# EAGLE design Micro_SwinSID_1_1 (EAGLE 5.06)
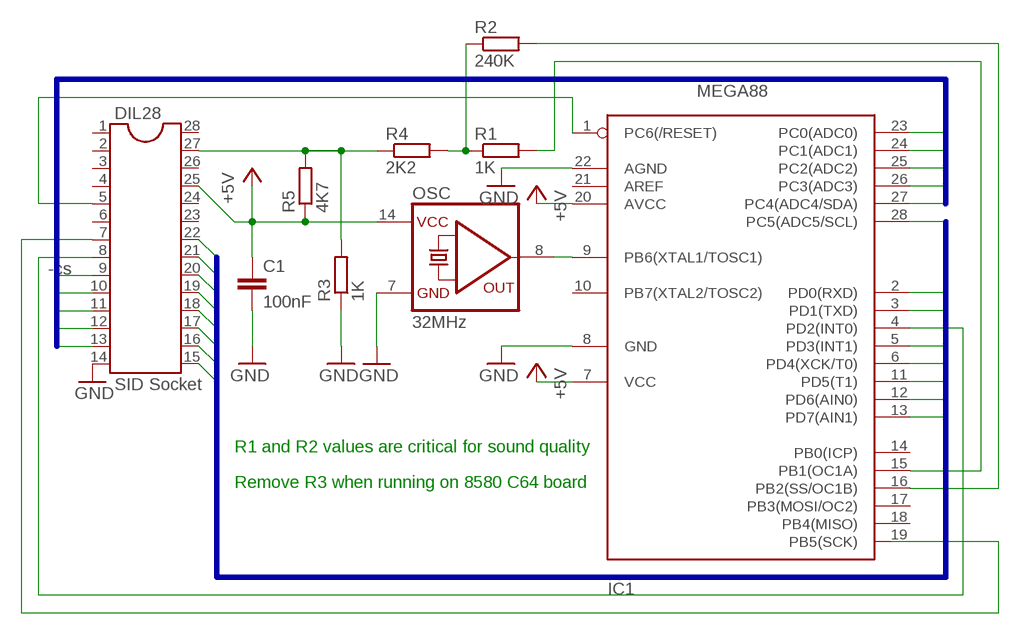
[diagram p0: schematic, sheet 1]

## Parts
C1  100nF  C2.5/2  [C2.5-2]
DIL28  SID Socket  DIL28  [DIL28-6]
IC1  MEGA88  MEGA8-P  [DIL28-3]
OSC  32MHz  QG5860  [DIL14S]
R1  1K  R-EU_0204/7  [0204/7]
R2  240K  R-EU_0204/7  [0204/7]
R3  1K  R-EU_0204/7  [0204/7]
R4  2K2  R-EU_0204/7  [0204/7]
R5  4K7  R-EU_0204/7  [0204/7]

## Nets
+5V: C1.1 DIL28.25 IC1.7(VCC) IC1.20(AVCC) OSC.14(VCC) R5.1
A0: DIL28.9 IC1.23(PC0(ADC0))
A1: DIL28.10 IC1.24(PC1(ADC1))
A2: DIL28.11 IC1.25(PC2(ADC2))
A3: DIL28.12 IC1.26(PC3(ADC3))
A4: DIL28.13 IC1.27(PC4(ADC4/SDA))
D0: DIL28.15 IC1.2(PD0(RXD))
D1: DIL28.16 IC1.3(PD1(TXD))
D2: DIL28.17 IC1.28(PC5(ADC5/SCL))
D3: DIL28.18 IC1.5(PD3(INT1))
D4: DIL28.19 IC1.6(PD4(XCK/T0))
D5: DIL28.20 IC1.11(PD5(T1))
D6: DIL28.21 IC1.12(PD6(AIN0))
D7: DIL28.22 IC1.13(PD7(AIN1))
GND: C1.2 DIL28.14 IC1.8(GND) IC1.22(AGND) OSC.7(GND) R3.1
N$1: IC1.9(PB6(XTAL1/TOSC1)) OSC.8(OUT)
N$2: DIL28.27 R3.2 R4.1 R5.2
N$3: R1.1 R2.1 R4.2
N$4: DIL28.7 IC1.19(PB5(SCK))
N$6: IC1.15(PB1(OC1A)) R1.2
N$7: IC1.16(PB2(SS/OC1B)) R2.2
N$11: DIL28.8 IC1.4(PD2(INT0))
P5: DIL28.5 IC1.1(PC6(/RESET))
Unconnected: DIL28.1 DIL28.2 DIL28.3 DIL28.4 DIL28.6 DIL28.23 DIL28.24 DIL28.26 DIL28.28 IC1.10(PB7(XTAL2/TOSC2)) IC1.14(PB0(ICP)) IC1.17(PB3(MOSI/OC2)) IC1.18(PB4(MISO)) IC1.21(AREF)

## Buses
DATA:D7,D6,D5,D4,D3,D2,D1,D0
ADR:A0,A1,A2,A3,A4

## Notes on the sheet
- -cs
- R1 and R2 values are critical for sound quality
- Remove R3 when running on 8580 C64 board

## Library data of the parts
C1 = capacitor-wima:C: CAPACITOR
DIL28 = ic-package:DIL28: Dual In Line
IC1 = atmel:MEGA8-P: MICROCONTROLLER 8 Kbytes FLASH, 1 kbytes SRAM, 512 bytes EEPROM, USART, 4-channel 10 bit ADC, 2-channel 8 bit ADC Pin compatible with Atmega48, ATMega88, ATMega168 Source: avr.lbr
OSC = crystal:QG5860: CRYSTAL RESONATOR
R1-R5 = rcl:R-EU_: RESISTOR, European symbol

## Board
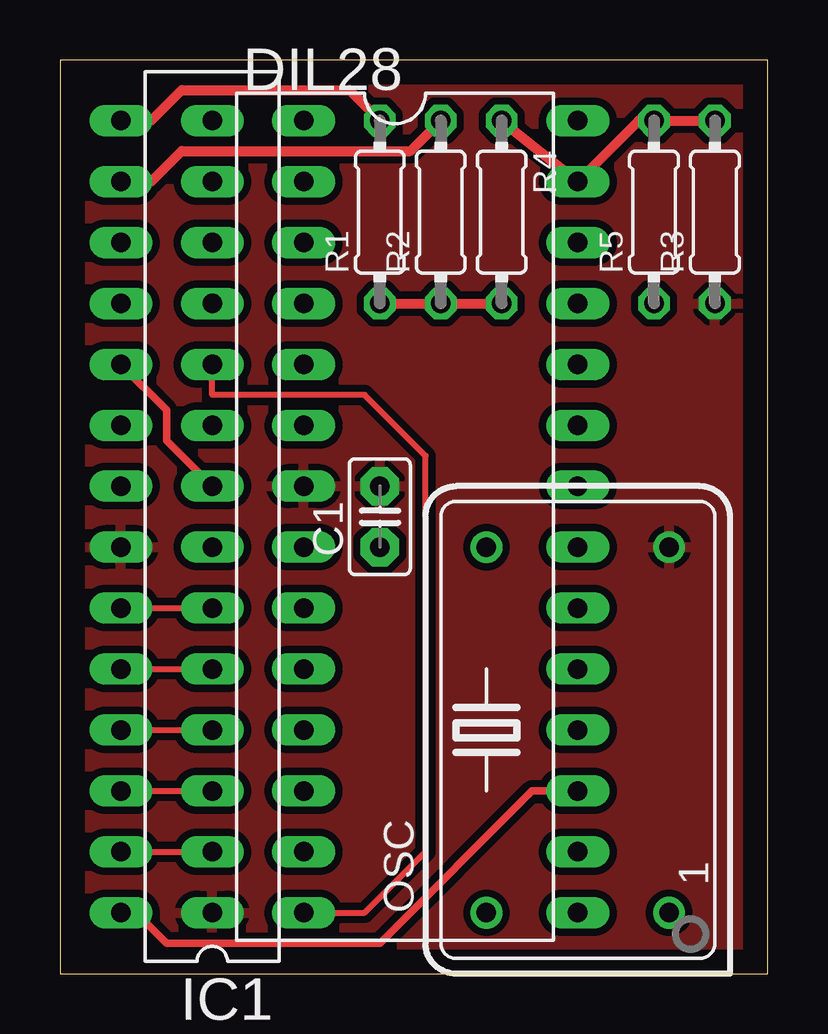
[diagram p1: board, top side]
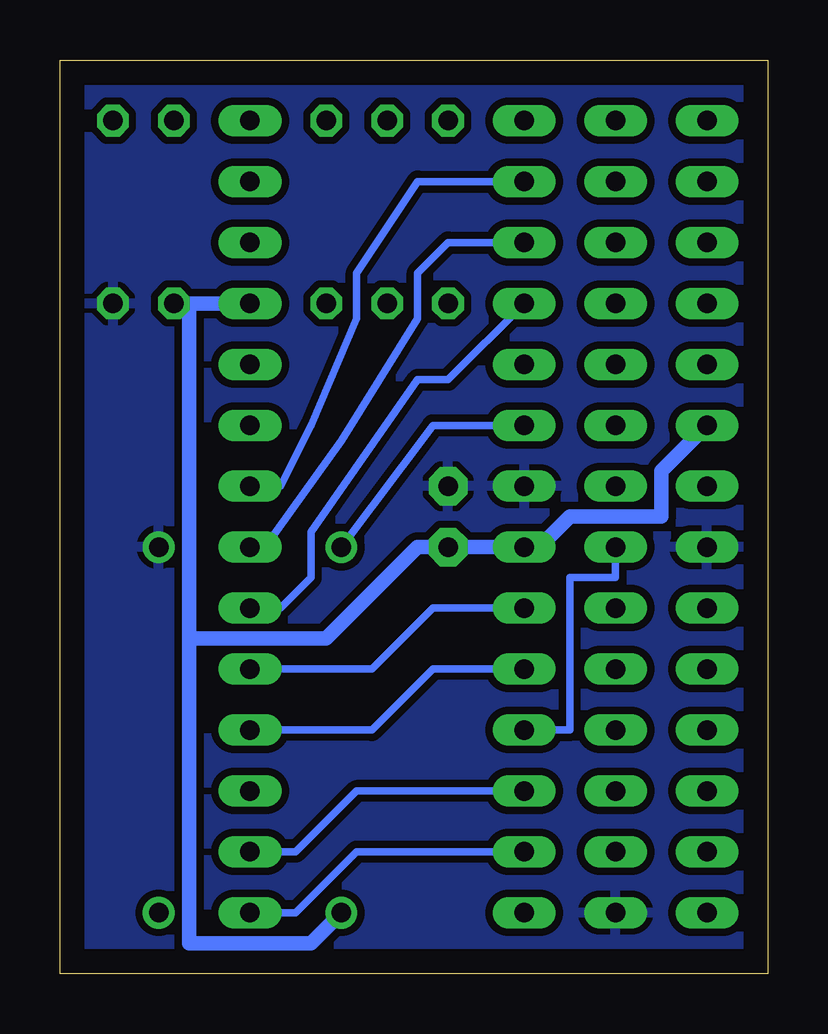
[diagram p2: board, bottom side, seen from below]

Size 29.52 x 38.09 mm. Coordinates in mm from the lower left corner, seen from the top.
Outline: 0,0 29.52,0 29.52,38.09 0,38.09 0,0
Copper layers (1*16): Top 0.035mm / dielectric 1.5mm / Bottom 0.035mm
Design rules "default": minimum track width 10mil, minimum drill 24mil, track to track 8mil, track to pad 8mil, pad to pad 8mil, via to via 8mil, smd to smd 8mil, copper to edge 40mil, drill to drill 8mil, minimum pad ring 10mil, minimum via ring 8mil, stop-mask expansion 4mil, vias tented up to drill 0mil, thermal gap 10mil

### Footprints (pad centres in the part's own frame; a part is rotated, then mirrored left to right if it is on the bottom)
C2.5-2 = drill 0.813 pad 1.6 octagon: 1 -1.27,0; 2 1.27,0
DIL28-6 = drill 0.813 long: 1 -16.51,-7.62; 2 -13.97,-7.62; 3 -11.43,-7.62; 4 -8.89,-7.62; 5 -6.35,-7.62; 6 -3.81,-7.62; 7 -1.27,-7.62; 8 1.27,-7.62; 9 3.81,-7.62; 10 6.35,-7.62; 11 8.89,-7.62; 12 11.43,-7.62; 13 13.97,-7.62; 14 16.51,-7.62; 15 16.51,7.62; 16 13.97,7.62; 17 11.43,7.62; 18 8.89,7.62; 19 6.35,7.62; 20 3.81,7.62; 21 1.27,7.62; 22 -1.27,7.62; 23 -3.81,7.62; 24 -6.35,7.62; 25 -8.89,7.62; 26 -11.43,7.62; 27 -13.97,7.62; 28 -16.51,7.62
DIL28-3 = drill 0.813 long: 1 -16.51,-3.81; 2 -13.97,-3.81; 3 -11.43,-3.81; 4 -8.89,-3.81; 5 -6.35,-3.81; 6 -3.81,-3.81; 7 -1.27,-3.81; 8 1.27,-3.81; 9 3.81,-3.81; 10 6.35,-3.81; 11 8.89,-3.81; 12 11.43,-3.81; 13 13.97,-3.81; 14 16.51,-3.81; 15 16.51,3.81; 16 13.97,3.81; 17 11.43,3.81; 18 8.89,3.81; 19 6.35,3.81; 20 3.81,3.81; 21 1.27,3.81; 22 -1.27,3.81; 23 -3.81,3.81; 24 -6.35,3.81; 25 -8.89,3.81; 26 -11.43,3.81; 27 -13.97,3.81; 28 -16.51,3.81
DIL14S = drill 0.813 round: 1 -7.62,-3.81; 7 7.62,-3.81; 8 7.62,3.81; 14 -7.62,3.81
0204/7 = drill 0.813 octagon: 1 -3.81,0; 2 3.81,0

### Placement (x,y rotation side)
C1  13.34,19.05 90 top
DIL28  13.97,19.05 270 top
IC1  6.35,19.05 90 top
OSC  21.59,10.16 90 top
R1  13.34,31.75 90 top
R2  15.88,31.75 90 top
R3  27.3,31.75 90 top
R4  18.41,31.75 270 top
R5  24.77,31.75 90 top

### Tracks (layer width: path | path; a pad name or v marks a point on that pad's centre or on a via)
+5V
  Bottom 0.406: 24.13,27.94 R5.1
  Bottom 0.61: 24.13,13.97 18.41,13.97 14.61,17.78 C1.1 IC1.7 9.52,17.78 8.25,19.05 4.45,19.05 4.45,20.96 IC1.20 | 24.13,13.97 24.13,27.94 | R5.1 DIL28.25 | OSC.14 19.05,1.27 24.13,1.27 24.13,13.97
A0
  Top 0.254: IC1.23 DIL28.9
A1
  Top 0.254: IC1.24 DIL28.10
A2
  Top 0.254: IC1.25 DIL28.11
A3
  Top 0.254: IC1.26 DIL28.12
A4
  Top 0.254: IC1.27 DIL28.13
D0
  Bottom 0.305: IC1.2 17.14,5.08 19.69,2.54 DIL28.15
D1
  Bottom 0.305: IC1.3 17.14,7.62 19.69,5.08 DIL28.16
D2
  Top 0.305: IC1.28 3.17,2.54 4.45,1.27 13.34,1.27 19.69,7.62 DIL28.17
D3
  Bottom 0.305: IC1.5 13.97,12.7 16.51,10.16 DIL28.18
D4
  Bottom 0.305: IC1.6 13.97,15.24 16.51,12.7 DIL28.19
D5
  Bottom 0.305: IC1.11 13.34,24.77 14.61,24.77 19.05,18.41 19.05,16.51 20.32,15.24 DIL28.20
D6
  Bottom 0.305: IC1.12 13.34,30.48 14.61,29.21 14.61,27.3 17.78,22.23 20.96,17.78 DIL28.21
D7
  Bottom 0.305: IC1.13 14.61,33.02 17.14,29.21 17.14,27.3 19.05,22.86 20.32,20.32 DIL28.22
GND
  pour Bottom (isolate 0.305): 0,38.1 29.84,38.1 29.84,0 0,0
  pour Top (isolate 0.305): 0,38.1 29.84,38.1 29.84,0 0,0
N$1
  Bottom 0.305: IC1.9 13.97,22.86 OSC.8
N$2
  Top 0.305: 24.13,35.56 R5.2
  Top 0.406: 24.13,35.56 DIL28.27 R4.1 | R5.2 R3.2
N$3
  Top 0.406: R1.1 R2.1 R4.2
N$4
  Top 0.305: IC1.19 4.45,23.5 4.45,22.23 DIL28.7
N$6
  Top 0.406: IC1.15 3.81,35.56 5.08,36.83 12.07,36.83 R1.2
N$7
  Top 0.406: IC1.16 3.81,33.02 5.08,34.29 14.61,34.29 R2.2
N$11
  Bottom 0.305: DIL28.8 6.35,16.51 8.25,16.51 8.25,10.16 IC1.4
P5
  Top 0.254: IC1.1 12.7,2.54 15.24,5.08 15.24,21.59 12.7,24.13 6.35,24.13 DIL28.5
